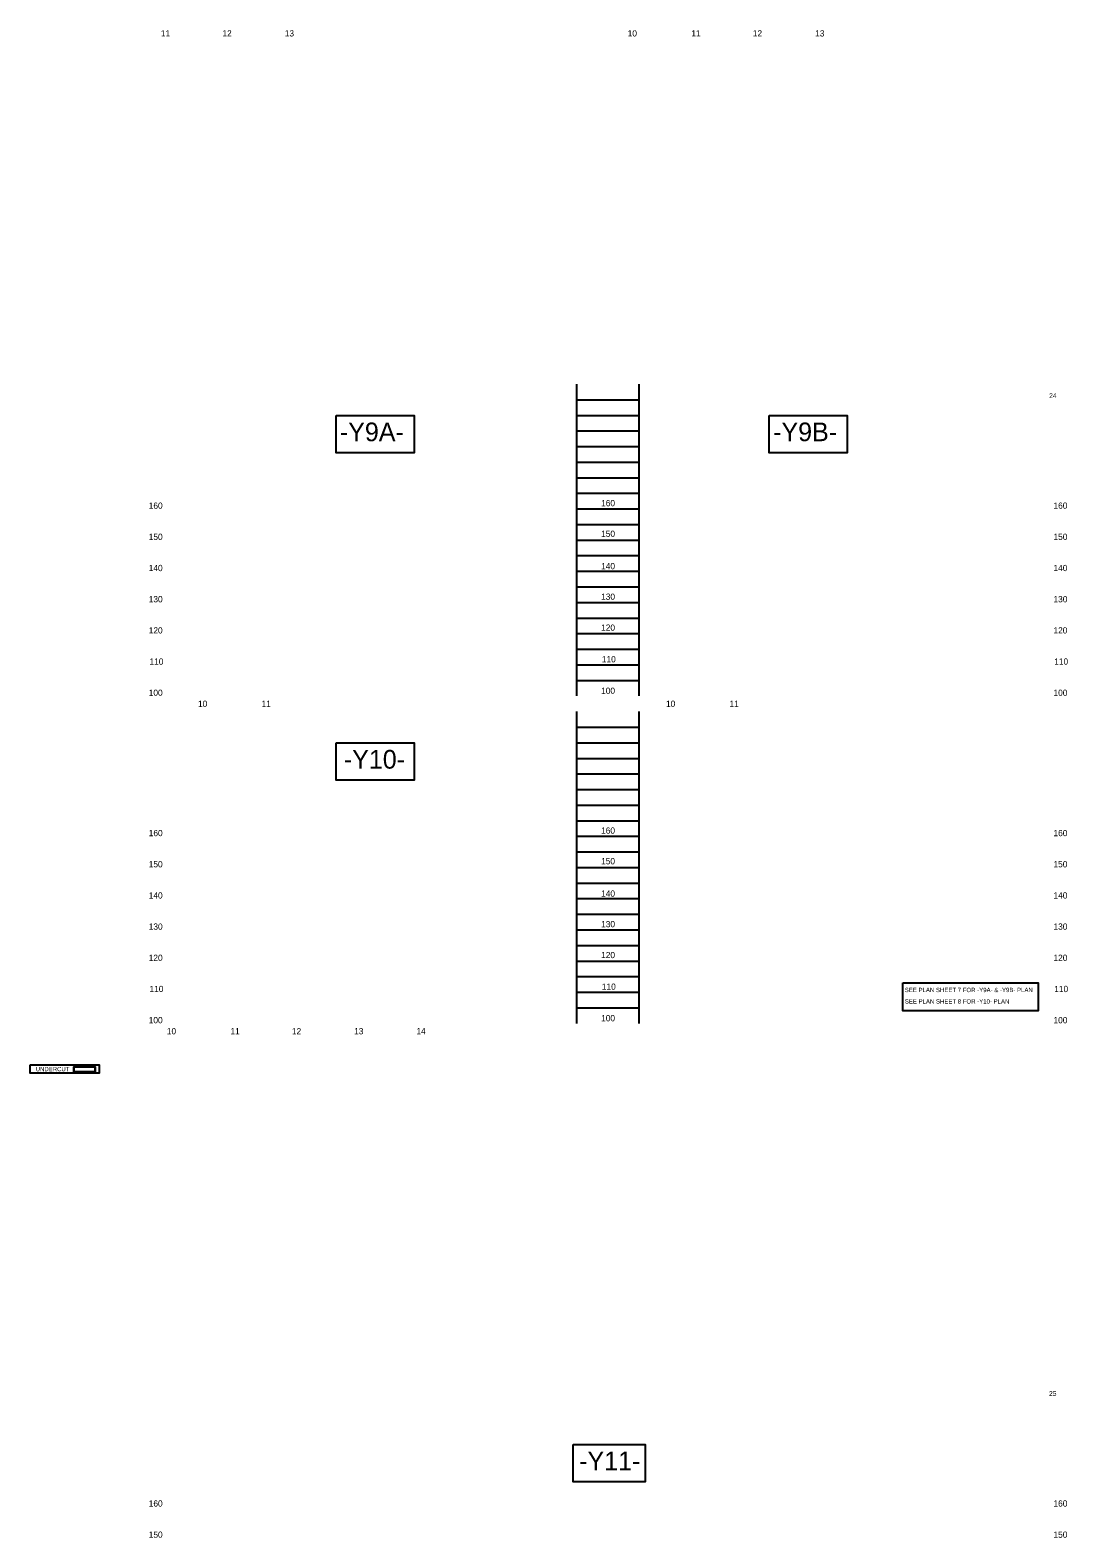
# Model space of a CAD drawing. Extents: x 2364289 to 2366249, y 588759 to 610062.
# Drawn here: x 2364289 to 2365952, y 593827 to 596244 of the extents above; entities that cross this region are included whole.
import ezdxf

# ---------------------------------------------------------------- set-up
doc = ezdxf.new("R2010")
doc.units = 0
for name, color, linetype in [('Exist Vertical Profile Horizontal Axis Label Major', 7, 'Continuous'), ('Exist Vertical Profile Vertical Axis Label', 7, 'Continuous'), ('Prop CMT Shallow Undercut', 7, 'Continuous'), ('Prop DSN Text', 7, 'Continuous'), ('Prop Grid Mask', 7, 'Continuous'), ('Sheet Data Field CELL', 7, 'Continuous'), ('Sheet Profile CELL', 7, 'Continuous'), ('Sheet Profile Grid Major CELL', 7, 'Continuous'), ('Sheet Profile Grid Middle CELL', 7, 'Continuous')]:
    doc.layers.add(name, color=color, linetype=linetype)

msp = doc.modelspace()

# ---------------------------------------------------------------- linework, layer by layer
at = {"layer": 'Prop CMT Shallow Undercut'}
msp.add_lwpolyline([(2364359, 594581.9), (2364393.2, 594581.9), (2364393.2, 594573.9), (2364359, 594573.9)], close=True, dxfattribs=at)
msp.add_lwpolyline([(2364359, 594581.9), (2364393.2, 594581.9), (2364393.2, 594573.9), (2364359, 594573.9)], close=True, dxfattribs=at)
msp.add_lwpolyline([(2364359, 594573.9), (2364393.2, 594573.9), (2364393.2, 594581.9), (2364359, 594581.9), (2364359, 594573.9)], dxfattribs=at)
msp.add_lwpolyline([(2364359, 594573.9), (2364393.2, 594573.9), (2364393.2, 594581.9), (2364359, 594581.9), (2364359, 594573.9)], dxfattribs=at)
at = {"layer": 'Prop Grid Mask'}
for points in [[(2364779.5, 595626.5), (2364904.5, 595626.5), (2364904.5, 595566.6), (2364779.5, 595566.6)], [(2365473.8, 595626.5), (2365598.8, 595626.5), (2365598.8, 595566.6), (2365473.8, 595566.6)], [(2364779.5, 595101.5), (2364904.5, 595101.5), (2364904.5, 595041.6), (2364779.5, 595041.6)], [(2365688, 594716.5), (2365904.6, 594716.5), (2365904.6, 594671.5), (2365688, 594671.5)], [(2364289.2, 594585), (2364399.9, 594585), (2364399.9, 594571.8), (2364289.2, 594571.8)], [(2365159.6, 593976.5), (2365274.8, 593976.5), (2365274.8, 593916.6), (2365159.6, 593916.6)]]:
    msp.add_lwpolyline(points, close=True, dxfattribs=at)
at = {"layer": 'Sheet Profile CELL'}
for p, q in [((2365164.6, 595676.5), (2365164.6, 595176.5)), ((2365264.6, 595676.5), (2365264.6, 595176.5)), ((2365164.6, 595151.5), (2365164.6, 594651.5)), ((2365264.6, 595151.5), (2365264.6, 594651.5))]:
    msp.add_line(p, q, dxfattribs=at)
at = {"layer": 'Sheet Profile Grid Major CELL'}
for p, q in [((2365164.6, 595626.5), (2365264.6, 595626.5)), ((2365164.6, 595576.5), (2365264.6, 595576.5)), ((2365164.6, 595526.5), (2365264.6, 595526.5)), ((2365164.6, 595476.5), (2365264.6, 595476.5)), ((2365164.6, 595426.5), (2365264.6, 595426.5)), ((2365164.6, 595376.5), (2365264.6, 595376.5)), ((2365164.6, 595326.5), (2365264.6, 595326.5)), ((2365164.6, 595276.5), (2365264.6, 595276.5)), ((2365164.6, 595226.5), (2365264.6, 595226.5)), ((2365164.6, 595101.5), (2365264.6, 595101.5)), ((2365164.6, 595051.5), (2365264.6, 595051.5)), ((2365164.6, 595001.5), (2365264.6, 595001.5)), ((2365164.6, 594951.5), (2365264.6, 594951.5)), ((2365164.6, 594901.5), (2365264.6, 594901.5)), ((2365164.6, 594851.5), (2365264.6, 594851.5)), ((2365164.6, 594801.5), (2365264.6, 594801.5)), ((2365164.6, 594751.5), (2365264.6, 594751.5)), ((2365164.6, 594701.5), (2365264.6, 594701.5))]:
    msp.add_line(p, q, dxfattribs=at)
at = {"layer": 'Sheet Profile Grid Middle CELL'}
for p, q in [((2365164.6, 595651.5), (2365264.6, 595651.5)), ((2365164.6, 595601.5), (2365264.6, 595601.5)), ((2365164.6, 595551.5), (2365264.6, 595551.5)), ((2365164.6, 595501.5), (2365264.6, 595501.5)), ((2365164.6, 595451.5), (2365264.6, 595451.5)), ((2365164.6, 595401.5), (2365264.6, 595401.5)), ((2365164.6, 595351.5), (2365264.6, 595351.5)), ((2365164.6, 595301.5), (2365264.6, 595301.5)), ((2365164.6, 595251.5), (2365264.6, 595251.5)), ((2365164.6, 595201.5), (2365264.6, 595201.5)), ((2365164.6, 595126.5), (2365264.6, 595126.5)), ((2365164.6, 595076.5), (2365264.6, 595076.5)), ((2365164.6, 595026.5), (2365264.6, 595026.5)), ((2365164.6, 594976.5), (2365264.6, 594976.5)), ((2365164.6, 594926.5), (2365264.6, 594926.5)), ((2365164.6, 594876.5), (2365264.6, 594876.5)), ((2365164.6, 594826.5), (2365264.6, 594826.5)), ((2365164.6, 594776.5), (2365264.6, 594776.5)), ((2365164.6, 594726.5), (2365264.6, 594726.5)), ((2365164.6, 594676.5), (2365264.6, 594676.5))]:
    msp.add_line(p, q, dxfattribs=at)

# ---------------------------------------------------------------- texts
at = {"layer": 'Exist Vertical Profile Horizontal Axis Label Major'}
for s, p in [('11', (2364498.7, 596234)), ('12', (2364597.3, 596234)), ('13', (2364697.2, 596234)), ('10', (2365246.8, 596234)), ('11', (2365348.8, 596234)), ('12', (2365447.3, 596234)), ('13', (2365547.2, 596234)), ('10', (2364558.2, 595159)), ('10', (2364558.2, 595159)), ('11', (2364660, 595159)), ('11', (2364660, 595159)), ('10', (2365308.2, 595159)), ('10', (2365308.2, 595159)), ('10', (2365308.2, 595159)), ('11', (2365410, 595159)), ('11', (2365410, 595159)), ('11', (2365410, 595159)), ('10', (2364508.2, 594634)), ('11', (2364610.1, 594634)), ('12', (2364708.7, 594634)), ('13', (2364808.4, 594634)), ('14', (2364908.2, 594634))]:
    msp.add_text(s, height=10, dxfattribs=at).set_placement(p)
at = {"layer": 'Exist Vertical Profile Vertical Axis Label'}
for s, p in [('160', (2365204.2, 595480.7)), ('160', (2364479.2, 595476.7)), ('160', (2365929.2, 595476.7)), ('150', (2365204.2, 595431.6)), ('150', (2364479.2, 595426.7)), ('150', (2365929.2, 595426.7)), ('140', (2364479.2, 595376.7)), ('140', (2365204.2, 595379.7)), ('140', (2365929.2, 595376.7)), ('130', (2364479.2, 595326.7)), ('130', (2365204.2, 595330.7)), ('130', (2365929.2, 595326.7)), ('120', (2364479.2, 595276.7)), ('120', (2365204.2, 595281.1)), ('120', (2365929.2, 595276.7)), ('110', (2364480.4, 595226.7)), ('110', (2365205.4, 595230.4)), ('110', (2365930.4, 595226.7)), ('100', (2364479.2, 595176.7)), ('100', (2365204.2, 595179.9)), ('100', (2365929.2, 595176.7)), ('160', (2364479.2, 594951.7)), ('160', (2365204.2, 594955.7)), ('160', (2365929.2, 594951.7)), ('150', (2364479.2, 594901.7)), ('150', (2365204.2, 594906.6)), ('150', (2365929.2, 594901.7)), ('140', (2364479.2, 594851.7)), ('140', (2365204.2, 594854.7)), ('140', (2365929.2, 594851.7)), ('130', (2364479.2, 594801.7)), ('130', (2365204.2, 594805.7)), ('130', (2365929.2, 594801.7)), ('120', (2365204.2, 594756.1)), ('120', (2364479.2, 594751.7)), ('120', (2365929.2, 594751.7)), ('110', (2365205.4, 594705.4)), ('110', (2364480.4, 594701.7)), ('110', (2365930.4, 594701.7)), ('100', (2364479.2, 594651.7)), ('100', (2365204.2, 594654.9)), ('100', (2365929.2, 594651.7)), ('160', (2364479.2, 593876.7)), ('160', (2365929.2, 593876.7)), ('150', (2364479.2, 593826.7)), ('150', (2365929.2, 593826.7))]:
    msp.add_text(s, height=10, dxfattribs=at).set_placement(p)
at = {"layer": 'Prop DSN Text'}
for s, p in [('SEE PLAN SHEET 7 FOR -Y9A- & -Y9B- PLAN', (2365690.9, 594701.6)), ('SEE PLAN SHEET 8 FOR -Y10- PLAN', (2365690.9, 594683.3)), ('UNDERCUT', (2364298, 594574.7))]:
    msp.add_text(s, height=7, dxfattribs=at).set_placement(p)
at = {"layer": 'Prop Grid Mask'}
for s, p in [('-Y9A-', (2364785.5, 595585)), ('-Y9B-', (2365479.9, 595585)), ('-Y10-', (2364791.9, 595060)), ('-Y11-', (2365169, 593935))]:
    msp.add_text(s, height=30, dxfattribs=at).set_placement(p)
at = {"layer": 'Sheet Data Field CELL'}
for s, p in [('24', (2365922.3, 595654.1)), ('25', (2365922.1, 594054.1))]:
    msp.add_text(s, height=7.75, dxfattribs=at).set_placement(p)

doc.saveas('drawing.dxf')
